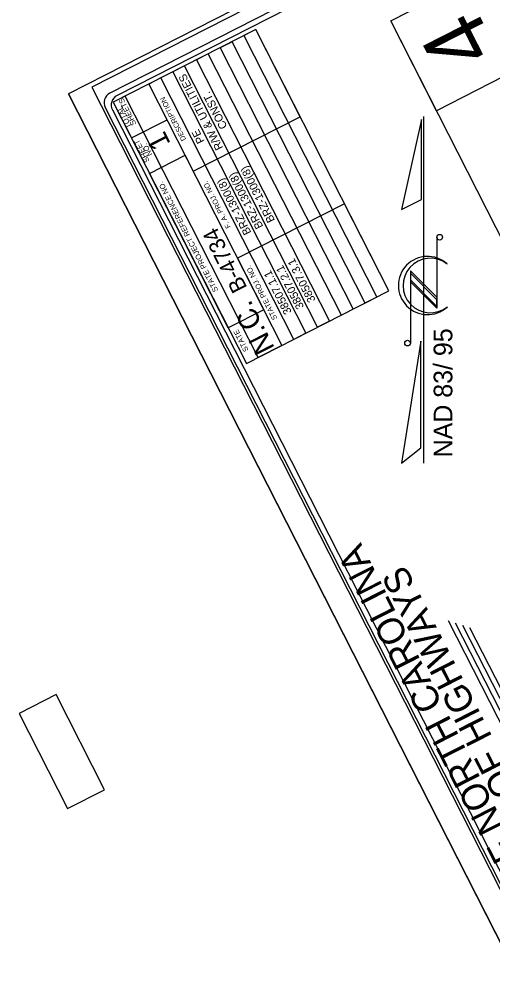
# Model space of a CAD drawing. Extents: x 558484 to 564063, y 513718 to 518374.
# Drawn here: x 558600 to 559044, y 515102 to 515996 of the extents above; entities that cross this region are included whole.
import ezdxf

# ---------------------------------------------------------------- set-up
doc = ezdxf.new("R2010")
doc.units = 0
for name, color, linetype in [('Default', 7, 'Continuous'), ('Prop Shade Heavy', 7, 'Continuous'), ('Sheet Cutting Line CELL', 7, 'Continuous'), ('Sheet Data Field CELL', 7, 'Continuous'), ('Sheet North Arrow CELL', 7, 'Continuous'), ('Sheet Plot Border Inside CELL', 7, 'Continuous'), ('Sheet Plot Border Outside CELL', 7, 'Continuous'), ('Sheet Title CELL', 7, 'Continuous')]:
    doc.layers.add(name, color=color, linetype=linetype)

msp = doc.modelspace()

# ---------------------------------------------------------------- linework, layer by layer
at = {"layer": 'Default'}
for points in [[(559444.47, 516246.59), (559867.25, 515416.18), (559371.15, 515163.61), (558948.37, 515994.01)], [(559036.28, 516038.77), (559079.22, 515954.42), (558991.31, 515909.66), (558948.37, 515994.01)]]:
    msp.add_lwpolyline(points, close=True, dxfattribs=at)
at = {"layer": 'Prop Shade Heavy'}
msp.add_lwpolyline([(558679.91, 515273.07), (558634.54, 515362.18), (558599.79, 515344.49), (558645.16, 515255.37)], close=True, dxfattribs=at)
at = {"layer": 'Sheet Cutting Line CELL'}
msp.add_line((559410.15, 514424.68), (558646.11, 515925.37), dxfattribs=at)
at = {"layer": 'Sheet North Arrow CELL'}
for p, q in [((558979.4, 515579.18), (558979.4, 515904.18)), ((558991.65, 515791.08), (558991.65, 515724.38)), ((559000.85, 515766.23), (559001.2, 515765.98)), ((558991.65, 515734.78), (558966.8, 515759.63)), ((558966.8, 515759.63), (558966.8, 515691.83)), ((558991.65, 515732.33), (558966.8, 515757.18)), ((558966.8, 515757.18), (558966.8, 515751.08)), ((558991.65, 515726.23), (558966.8, 515751.08)), ((558966.8, 515751.08), (558991.65, 515726.23)), ((558991.65, 515724.38), (558966.8, 515749.23)), ((558991.65, 515726.23), (558991.65, 515732.33))]:
    msp.add_line(p, q, dxfattribs=at)
for points in [[(558977.15, 515901.33), (558958.6, 515816.93), (558977.15, 515826.33)], [(558976.75, 515693.68), (558958.35, 515579.18), (558976.75, 515593.68)]]:
    msp.add_lwpolyline(points, close=True, dxfattribs=at)
for centre in [(558994.3, 515791.02), (558964.15, 515691.72)]:
    msp.add_circle(centre, 2.65, dxfattribs=at)
for centre, radius, start, end in [((558982.86, 515745.74), 27.3, 47.84002, 312.39406), ((558985.5, 515745.75), 25.59, 53.09504, 308.62871)]:
    msp.add_arc(centre, radius, start, end, dxfattribs=at)
at = {"layer": 'Sheet Plot Border Inside CELL'}
msp.add_lwpolyline([(560364.51, 514925.16), (559608.41, 516410.26), (558668.16, 515931.55), (559424.26, 514446.45)], close=True, dxfattribs=at)
at = {"layer": 'Sheet Plot Border Outside CELL'}
msp.add_lwpolyline([(558646.11, 515925.37), (559410.15, 514424.68), (560390.41, 514923.75), (559626.36, 516424.45)], close=True, dxfattribs=at)
at = {"layer": 'Sheet Title CELL'}
for p, q in [((559153.51, 515134.95), (559002.53, 515431.47)), ((559155.69, 515141.67), (559009.26, 515429.29)), ((559157.89, 515148.4), (559015.98, 515427.1)), ((559160.07, 515155.12), (559022.7, 515424.91))]:
    msp.add_line(p, q, dxfattribs=at)
for points in [[(559602.88, 516393.42), (558685.01, 515926.1)], [(559435.85, 516302.76), (558691.72, 515923.91)], [(558946.63, 515740.61), (558821.86, 515985.68), (558810.74, 515980.01), (558935.49, 515734.94), (558924.37, 515729.28), (558799.6, 515974.34), (558788.46, 515968.67), (558913.22, 515723.62), (558902.08, 515717.93), (558777.31, 515962.99), (558766.17, 515957.32), (558890.94, 515712.26), (558879.81, 515706.59), (558755.03, 515951.65), (558743.9, 515945.99), (558868.67, 515700.92), (558857.53, 515695.25), (558732.76, 515940.32), (558721.61, 515934.64), (558846.38, 515689.57), (558824.1, 515678.23), (558699.33, 515923.3), (558688.19, 515917.62), (558812.97, 515672.56), (558946.63, 515740.61), (558905.06, 515822.29), (558804.81, 515771.25), (558829.38, 515723), (558795.95, 515705.98), (558722.23, 515850.8), (558755.64, 515867.8), (558763.22, 515852.92), (558863.47, 515903.96), (558821.86, 515985.68), (558688.19, 515917.62), (558705.21, 515884.21), (558738.62, 515901.23)], [(558680.63, 515912.67), (559352.12, 514593.74)], [(558687.36, 515910.47), (559331.62, 514645.05)]]:
    msp.add_lwpolyline(points, dxfattribs=at)
for centre in [(558689.49, 515917.17), (558696.22, 515914.98)]:
    msp.add_arc(centre, 10, 116.98193, 206.98193, dxfattribs=at)

# ---------------------------------------------------------------- texts
at = {"layer": 'Default'}
msp.add_text('4', height=60, rotation=116.98193, dxfattribs=at).set_placement((559047.89, 515966.96))
at = {"layer": 'Sheet Data Field CELL'}
for s, height, p in [('R/W & UTILITIES', 7.5, (558791.35, 515874.91)), ('CONST.    ', 7.5, (558795.32, 515894.66)), ('PE        ', 7.5, (558774.06, 515881.12)), ('BRZ-1300(8)   ', 7.5, (558828.95, 515801.09)), ('BRZ-1300(8)   ', 7.5, (558839.96, 515806.98)), ('BRZ-1300(8)   ', 7.5, (558817.81, 515795.42)), ('B-4734    ', 15, (558814.1, 515743.74)), ('38507.3.1 ', 7.5, (558878.09, 515732.1)), ('38507.2.1 ', 7.5, (558867.28, 515725.8)), ('38507.1.1 ', 7.5, (558855.73, 515720.93))]:
    msp.add_text(s, height=height, rotation=116.98193, dxfattribs=at).set_placement(p)
at = {"layer": 'Sheet North Arrow CELL'}
msp.add_text('NAD 83/ 95', height=17.5, rotation=90, dxfattribs=at).set_placement((559006.15, 515584.62))
at = {"layer": 'Sheet Title CELL'}
for s, height, p in [('SHEETS', 5, (558709.95, 515897.27)), ('DESCRIPTION', 4.8, (558756.64, 515882.73)), ('TOTAL', 5, (558705.64, 515894.7)), ('1', 19.35, (558742.34, 515878.82)), ('SHEET', 5, (558722.39, 515862.6)), ('NO.', 5, (558724.91, 515868.54)), ('STATE PROJECT REFERENCE NO.', 4.9998, (558786.71, 515741.22)), ('F. A. PROJ. NO.', 4.8, (558798.41, 515800.65)), ('STATE PROJ. NO.', 4.8, (558842.1, 515714.83)), ('N.C.', 19.35, (558839.94, 515687.13)), ('STATE', 5, (558815.22, 515685.21)), ('STATE OF NORTH CAROLINA', 24.9999, (559134.15, 515084.92)), ('DIVISION OF HIGHWAYS', 24.9999, (559140.09, 515133.84))]:
    msp.add_text(s, height=height, rotation=116.98193, dxfattribs=at).set_placement(p)

doc.saveas('drawing.dxf')
